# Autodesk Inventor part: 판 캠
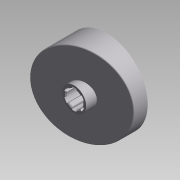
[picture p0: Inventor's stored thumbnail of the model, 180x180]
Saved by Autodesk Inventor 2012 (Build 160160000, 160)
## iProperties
Created: 2012-05
Part Number: 판 캠
Document SubType Name: 모델링
Designer: SeoGD™
Material: 강
Mass: 681.586 g
Surface Area: 331.302 cm^2
Volume: 86.8262 cm^3
Density: 7.85 g/cm^3
변환 표준: STEP AP214IS
파일 이름: C:\Users\SeoGD\Desktop\?쒗뿕\??stp
전처리기: Build: 253, Release: 2010 SP1 - Date: Wed 07/29/2009
전송 단위: 밀리미터
불확실성: 0.01
Author: SeoGD™
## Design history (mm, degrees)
node "작업 평면4"
sketch "스케치1"
  geometry: C1 r 44.5 at (0, 0); 1 further point
  constraints: 1 centre point, 1 coincident
  dimensions: "d25" = 89 diameter of C1
extrude "돌출1" new body sketch "스케치1" distance "d1" = 40; taper "d2" = 0 deg
sketch "스케치2"
  geometry: L1 (-44.5, 15)-(44.5, 38.847); L2 (-44.5, 0)-(-44.5, 40) reference; L3 (-44.5, 40)-(44.5, 40) reference; L4 (44.5, 0)-(44.5, 40) reference; 1 further point
  constraints: 2 end point, 2 point on line
  dimensions: "d26" = 15 distance of L2.start L1.start; "d27" = 75 deg angle of L1 L2
extrude "돌출2" cut sketch "스케치2" stored distance "d5" = 40; taper "d6" = 0 deg
node "작업 평면1"
sketch "스케치3"
  geometry: C1 r 13 at (0, 0); 1 further point
  constraints: 1 centre point, 1 coincident
  dimensions: "d9" = 26 diameter of C1
extrude "돌출3" join sketch "스케치3" distance "d10" = 38; taper "d11" = 0 deg
hole "구멍1" diameter "d14" = 18; stored, may be unused: countersink angle "d18" = 90 deg, drill point angle "d20" = 118 deg; dims "d12" = 10, "d13" = 10, "d15" = 6, "d16" = 4, "d17" = 2, "d19" = 8
feature "쉘2" dims "d29" = 5
sketch "스케치6"
  geometry: C1 r 17.5 at (0, 0); C2 r 14 at (0, 0) reference; 1 further point
  constraints: 1 centre point, 1 coincident
  dimensions: "d28" = 35 diameter of C1
extrude "돌출4" join sketch "스케치6" stored distance "d30" = 38; taper "d31" = 0 deg
fillet "모깎기1" dims "d32" = 3
chamfer "모따기1" distance "d21" = 1; stored, may be unused: second distance "d22" = 2, angle "d23" = 45 deg
sketch "스케치7"
  geometry: L1 (-12.374, 12.374)-(-27.931, 27.931); A1 r 39.5 centre (0, 0) between (-27.931, 27.931) and (0, 39.5) reference; 2 further points
  constraints: 2 end point, 2 point on circle, 1 point on line, 1 vertical alignment, 2 other
  dimensions: "d33" = 45 deg dimension on point (0, 0) L1.start A1.end
feature "리브1" sketch "스케치7" dims "d34" = 5, "d35" = 1, "d36" = 0
fillet "모깎기2" dims "d37" = 3
sketch "스케치8"
  geometry: L1 (2.5, 10.712)-(2.5, 8.646); L2 (-2.5, 10.712)-(-2.5, 8.646); A1 r 11 centre (0, 0) between (2.5, 10.712) and (-2.5, 10.712); A2 r 9 centre (0, 0) between (2.5, 8.646) and (-2.5, 8.646) reference; 1 further point
  constraints: 4 end point, 4 point on circle, 2 parallel, 1 centre point, 1 coincident, 1 vertical
  dimensions: "d41" = 22 diameter of A1; "d42" = 5 distance between parallel lines of L1 L2
extrude "돌출5" cut sketch "스케치8" stored distance "d43" = 38; taper "d44" = 0 deg
fillet "모깎기3" dims "d48" = 1
node "솔리드1"
node "솔리드 본체"
node "곡면 본체"
pattern_circular "원형 패턴1" dims angle "d39" = 360 deg
pattern_circular "원형 패턴2" dims angle "d46" = 360 deg
node "솔리드2"
